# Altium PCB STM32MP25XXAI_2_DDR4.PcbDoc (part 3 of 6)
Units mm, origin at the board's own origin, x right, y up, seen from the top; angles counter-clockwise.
Board outline 172 x 137 mm, 4 copper layers (Top Layer, Signal Layer 1, Signal Layer 2, Bottom Layer), stack 1.614 mm thick; 241 components, 153 nets, 1312 pads, 924 vias.
Unrouted connection lines stored in the file: 13.
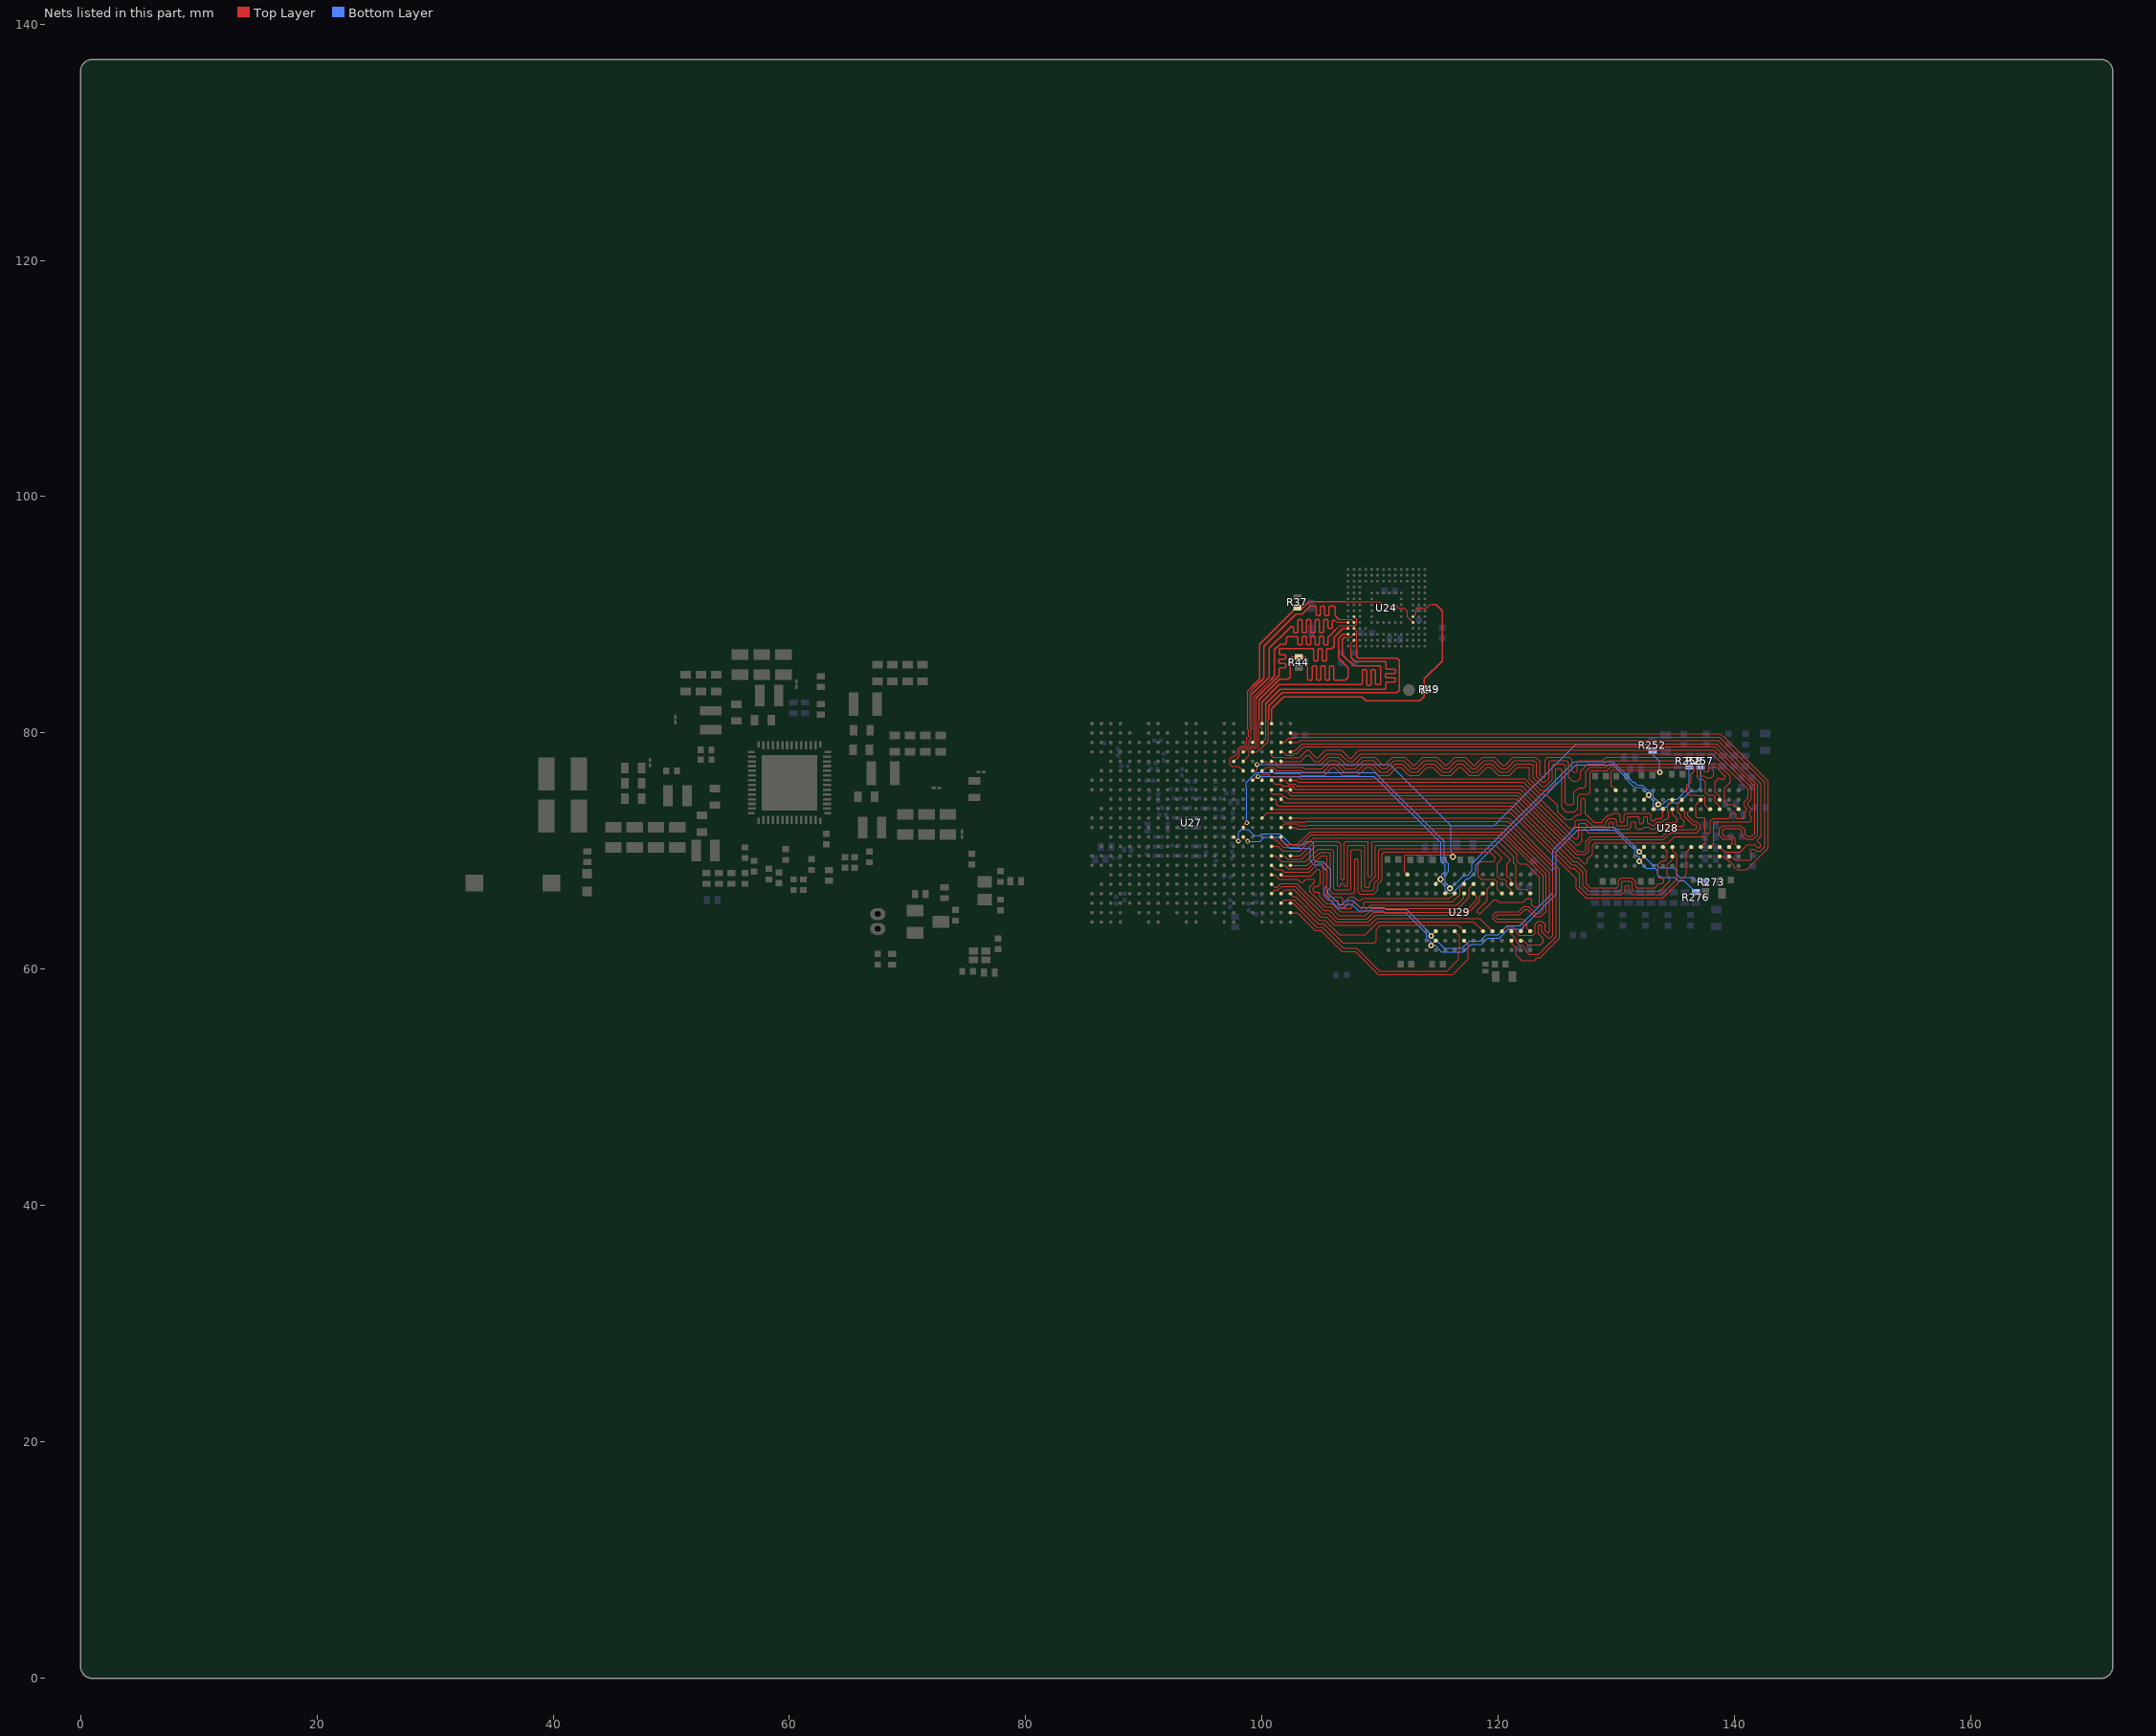
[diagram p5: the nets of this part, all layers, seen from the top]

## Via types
v1: diameter 0.55, hole 0.35, Top Layer to Bottom Layer, 432 vias
v2: diameter 0.4, hole 0.2, Top Layer to Bottom Layer, tented both sides, 202 vias
v3: diameter 0.5, hole 0.2, Top Layer to Bottom Layer, 146 vias
v4: diameter 0.5, hole 0.25, Top Layer to Bottom Layer, 144 vias

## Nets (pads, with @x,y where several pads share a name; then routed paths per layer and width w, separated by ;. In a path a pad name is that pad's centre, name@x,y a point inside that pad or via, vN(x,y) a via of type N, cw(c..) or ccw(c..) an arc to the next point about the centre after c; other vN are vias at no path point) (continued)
DDR_CSN: R273.1 U27.N16 U28.L7 U29.L7 | length 57.8
  Top Layer w0.09: U27.N16@97.6,71.2 97.625,71.2 97.975,70.85 v2(98,70.85) ; v4(114.3,62.825) 114.332,62.825 114.669,63.163 U29.L7@114.669,63.224 ; v4@131.963,69.928 132.301,70.266 U28.L7@132.301,70.327
  Bottom Layer w0.09: v2(98,70.85) 98,71.6 98.25,71.85 98.8,71.85 99.352,71.298 99.779,71.298 99.941,71.46 101.546,71.46 102.453,70.553 103.528,70.553 103.8,70.825 104.25,70.825 104.371,70.704 104.371,69.286 104.55,69.108 105.14,69.108 105.805,68.443 105.805,66.98 105.575,66.75 105.575,66.444 106.54,65.479 106.78,65.479 107.125,65.825 107.675,65.825 108.275,65.225 110.332,65.225 110.497,65.06 112.215,65.06 114.3,62.975 v4(114.3,62.825) 114.3,62.775 114.65,62.425 114.754,62.425 115.407,61.772 116.937,61.772 117.57,62.405 118.464,62.405 118.987,62.928 119.976,62.928 120.741,63.693 121.837,63.693 124.62,66.476 124.62,70.106 126.564,72.05 129.853,72.05 131.368,70.535 131.911,69.991 131.911,69.978 131.925,69.964 v4(131.925,69.95) 133.036,68.839 133.4,68.839 133.632,68.607 134.35,68.607 ; 134.35,68.606 134.853,68.606 135.095,68.364 135.095,68.046 135.337,67.805 136.42,67.805 136.85,67.375 R273.1@137.55,67.375
DDR_DQ0: U27.W22 U29.F7 | length 18.5
  Top Layer w0.09: U27.W22@102.4,66.4 102.615,66.185 102.82,66.185 104.862,64.144 105.339,64.144 106.556,62.927 108.753,62.927 109.836,64.01 117.908,64.01 U29.F7@118.682,63.237
DDR_DQ1: U27.Y21 U29.H7 | length 18.5
  Top Layer w0.09: U27.Y21@101.6,65.6 101.6,65.628 101.867,65.895 102.7,65.895 104.741,63.854 105.219,63.854 106.826,62.246 109.511,62.246 109.669,62.405 109.669,63.377 110.012,63.72 116.596,63.72 U29.H7@117.094,63.222
DDR_DQ2: U27.Y22 U29.J7 | length 19.6
  Top Layer w0.09: U27.Y22@102.4,65.6 102.419,65.581 102.604,65.581 104.621,63.564 105.098,63.564 106.884,61.778 108.022,61.778 109.953,59.847 115.648,59.847 116.651,60.851 116.651,61.417 116.695,61.461 116.695,62.82 U29.J7@116.294,63.222
DDR_DQ3: U27.AA22 U29.H8 | length 19.5
  Top Layer w0.09: U27.AA22@102.4,64.8 102.975,64.8 104.501,63.274 104.978,63.274 106.764,61.488 107.902,61.488 109.843,59.547 116.149,59.547 117.453,60.851 117.453,62.063 U29.H8@117.094,62.422
DDR_DQ4: U27.T21 U29.J3 | length 20
  Top Layer w0.09: U27.T21@101.6,68.8 101.942,68.8 102.237,68.505 103.899,68.505 104.992,69.599 105.381,69.599 105.501,69.478 105.501,66.319 105.686,66.134 106.676,66.134 106.835,65.974 106.835,65.53 106.934,65.432 107.071,65.432 107.232,65.593 107.232,65.957 107.413,66.137 107.785,66.137 108.072,65.85 108.382,65.85 108.536,66.003 115.875,66.003 U29.J3@116.294,66.422
DDR_DQ5: U27.T20 U29.H2 | length 22.2
  Top Layer w0.09: U27.T20@100.8,68.8 101.182,68.418 101.67,68.418 101.873,68.215 104.019,68.215 104.777,68.973 105.038,68.973 105.139,68.872 105.139,68.517 105.211,68.445 105.211,66.198 105.566,65.844 106.371,65.844 106.423,65.791 106.423,65.463 106.744,65.142 107.523,65.142 107.576,65.195 107.576,65.527 107.706,65.658 107.848,65.658 108.364,65.142 108.498,65.142 108.612,65.256 108.612,65.628 108.697,65.713 116.104,65.713 116.735,66.345 116.735,66.864 U29.H2@117.094,67.222
DDR_DQ6: U27.U21 U29.H3 | length 20.3
  Top Layer w0.09: U27.U21@101.604,68.004 101.682,67.925 104.139,67.925 104.682,68.468 104.778,68.468 104.921,68.325 104.921,67.221 104.7,67 104.463,67 104.315,66.852 104.315,66.684 104.462,66.537 104.773,66.537 104.888,66.422 104.888,66.111 105.446,65.554 105.923,65.554 106.624,64.852 108.618,64.852 109.189,65.423 116.482,65.423 117.094,66.035 U29.H3@117.094,66.422
DDR_DQ7: U27.U20 U29.G2 | length 21.4
  Top Layer w0.09: U27.U20@100.8,68 101.078,68 101.452,67.626 103.005,67.626 103.231,67.4 103.475,67.4 103.7,67.626 104.375,67.626 104.428,67.573 104.428,67.375 104.025,66.972 104.025,66.564 105.326,65.264 105.803,65.264 106.504,64.562 108.738,64.562 109.309,65.133 116.602,65.133 117.544,66.074 117.544,66.872 U29.G2@117.894,67.222
DDR_DQ8: U27.M21 U29.B8 | length 36
  Top Layer w0.09: U27.M21@101.6,72 101.903,72.303 102.947,72.303 103.083,72.168 103.776,72.168 103.826,72.217 120.651,72.217 124.615,68.253 124.615,62.892 124.4,62.676 124.174,62.676 123.679,63.171 123.679,63.692 123.59,63.78 123.468,63.78 123.384,63.696 123.384,62.988 123.795,62.577 123.795,62.32 123.55,62.075 122.461,62.075 122.151,62.386 121.93,62.386 U29.B8@121.894,62.422
DDR_DQ9: U27.M22 U29.D7 | length 34.8
  Top Layer w0.09: U27.M22@102.4,72 102.84,72 102.963,71.878 103.896,71.878 103.946,71.927 120.531,71.927 124.325,68.133 124.325,63.15 124.255,63.08 124.18,63.08 123.969,63.291 123.969,63.812 123.711,64.07 123.348,64.07 123.094,63.817 123.094,63.063 122.908,62.877 121.751,62.877 121.474,63.154 121.474,63.339 121.241,63.573 120.644,63.573 U29.D7@120.294,63.222
DDR_DQ10: U27.L21 U29.C7 | length 36.4
  Top Layer w0.09: U27.L21@101.6,72.8 101.9,72.5 103.16,72.5 103.203,72.458 103.656,72.458 103.706,72.507 120.771,72.507 124.905,68.373 124.905,62.771 123.411,61.277 122.596,61.277 122.321,61.552 122.321,61.708 122.007,62.022 121.806,62.022 121.521,62.307 121.521,62.523 121.094,62.951 U29.C7@121.094,63.222
DDR_DQ11: U27.L22 U29.C8 | length 36.5
  Top Layer w0.09: U27.L22@102.403,72.797 120.891,72.797 125.195,68.493 125.195,62.651 123.531,60.987 123.257,60.987 123.025,60.755 121.984,60.755 121.984,60.758 121.507,61.234 121.507,61.777 121.15,62.134 121.15,62.375 U29.C8@121.1,62.425
DDR_DQ12: U27.T22 U29.D3 | length 35.7
  Top Layer w0.09: U27.T22@102.4,68.8 103.783,68.8 104.872,69.889 105.737,69.889 105.791,69.835 105.791,66.585 105.949,66.427 107.716,66.427 107.827,66.538 107.827,69.263 107.91,69.347 108.01,69.347 108.123,69.233 108.123,66.54 108.296,66.367 109.46,66.367 109.78,66.687 109.78,67.164 110.164,67.547 110.164,69.788 110.313,69.937 119.279,69.937 119.719,69.497 119.719,69.239 119.587,69.108 118.533,69.108 118.305,68.88 118.305,67.858 118.541,67.622 119.665,67.622 119.924,67.363 119.924,66.792 U29.D3@120.294,66.422
DDR_DQ13: U27.R20 U29.C3 | length 37.4
  Top Layer w0.09: U27.R20@100.8,69.6 101.138,69.6 101.636,69.102 103.675,69.102 104.765,70.192 105.844,70.192 106.081,69.955 106.081,66.825 106.188,66.717 107.424,66.717 107.537,66.83 107.537,70.029 107.653,70.145 108.296,70.145 108.413,70.028 108.413,66.754 108.51,66.657 109.34,66.657 109.49,66.807 109.49,67.284 109.874,67.667 109.874,70.049 110.052,70.227 119.483,70.227 120.263,69.447 120.269,69.447 120.269,69.337 119.902,68.97 119.902,67.875 120.149,67.628 120.538,67.628 120.694,67.472 120.694,67.085 121.08,66.698 121.08,66.436 U29.C3@121.094,66.422
DDR_DQ14: U27.R21 U29.C2 | length 36.8
  Top Layer w0.09: U27.R21@101.6,69.6 101.893,69.6 102.189,69.304 103.346,69.304 104.56,70.517 106.284,70.517 106.371,70.431 106.371,67.089 106.453,67.007 106.566,67.007 106.661,67.102 106.661,67.233 106.737,67.309 106.852,67.309 106.957,67.204 106.957,67.082 107.031,67.007 107.158,67.007 107.247,67.096 107.247,70.431 107.333,70.517 108.633,70.517 108.703,70.447 108.703,67.035 108.791,66.947 109.031,66.947 109.121,67.037 109.121,67.358 109.584,67.821 109.584,70.439 109.662,70.517 119.769,70.517 120.994,69.292 120.994,69.186 120.704,68.897 120.704,67.924 121.094,67.534 U29.C2@121.094,67.222
DDR_DQ15: U27.R22 U29.A3 | length 35.9
  Top Layer w0.09: U27.R22@102.4,69.6 103.232,69.6 104.44,70.807 106.441,70.807 106.661,70.587 106.661,67.682 106.743,67.599 106.876,67.599 106.957,67.68 106.957,70.705 107.059,70.807 108.94,70.807 108.993,70.754 108.993,67.867 109.046,67.814 109.167,67.814 109.294,67.941 109.294,70.754 109.346,70.807 120.01,70.807 121.286,69.532 121.286,68.986 121.495,68.776 121.495,66.99 121.709,66.776 122.34,66.776 U29.A3@122.694,66.422
DDR_DQ16: U27.D20 U28.D7 | length 52.3
  Top Layer w0.09: U27.D20@100.8,78.4 100.8,78.074 100.912,77.962 ; 100.913,77.963 101.838,77.963 101.908,77.892 103.143,77.892 103.791,78.54 103.925,78.54 104.573,77.892 104.712,77.892 105.36,78.54 106.715,78.54 107.399,77.856 107.546,77.856 108.231,78.54 138.22,78.54 141.412,75.348 141.412,74.373 ; U28.D7@137.925,70.35 137.925,70.366 138.23,70.67 138.23,72.412 138.282,72.465 141.261,72.465 141.413,72.617 141.413,72.863 141.236,73.04 141.236,73.285 141.413,73.462 141.413,73.593 141.093,73.913 141.093,74.052 141.413,74.372
DDR_DQ17: U27.C22 U28.C7 | length 50.9
  Top Layer w0.09: U27.C22@102.4,79.2 103.106,79.2 103.277,79.37 138.564,79.37 142.243,75.691 142.243,71.27 141.949,70.976 141.949,70.826 142.191,70.585 142.191,70.427 142.067,70.304 141.924,70.304 141.703,70.525 141.072,70.525 140.468,69.921 139.13,69.921 U28.C7@138.725,70.325
DDR_DQ18: U27.C21 U28.B8 | length 52.6
  Top Layer w0.09: U27.C21@101.6,79.2 101.897,79.2 102.272,79.575 102.725,79.575 102.811,79.66 138.684,79.66 142.533,75.812 142.533,70.359 142.188,70.014 141.804,70.014 141.631,70.187 141.402,70.187 141.318,70.103 141.318,69.932 141.47,69.78 141.47,69.366 141.332,69.228 140.047,69.228 139.78,69.495 139.58,69.495 U28.B8@139.525,69.55
DDR_DQ19: U27.B22 U28.C8 | length 53.2
  Top Layer w0.09: U27.B22@102.4,80 102.45,79.95 138.804,79.95 139.04,79.715 142.823,75.932 142.823,70.239 141.014,68.43 140.193,68.43 139.93,68.693 139.93,68.798 139.568,69.16 139.463,69.16 139.073,69.55 U28.C8@138.725,69.55
DDR_DQ20: U27.F20 U28.D3 | length 54.2
  Top Layer w0.09: U27.F20@100.8,76.8 101.025,76.575 103.14,76.575 103.309,76.406 105.277,76.406 105.961,77.09 106.115,77.09 106.799,76.406 108.147,76.406 108.831,77.09 109.181,77.09 109.865,76.406 110.711,76.406 111.395,77.09 111.74,77.09 112.424,76.406 113.261,76.406 113.945,77.09 114.465,77.09 115.149,76.406 115.986,76.406 116.67,77.09 116.843,77.09 117.527,76.406 118.352,76.406 119.036,77.09 119.305,77.09 119.989,76.406 120.936,76.406 121.62,77.09 122.6,77.09 122.646,77.045 122.646,76.1 123.574,75.172 124.284,75.172 124.865,75.753 124.865,76.89 125,77.025 125.225,77.025 125.376,76.875 125.376,73.68 125.721,73.335 126.42,73.335 126.7,73.615 126.7,74.601 126.925,74.825 127.6,74.825 127.755,74.98 127.755,76.67 127.881,76.796 129.196,76.796 129.49,77.09 136.46,77.09 136.545,77.005 136.545,76.795 136.3,76.55 136.3,75.9 135.95,75.55 135.95,74.96 136.15,74.761 136.786,74.761 136.852,74.695 137.323,74.695 137.47,74.548 137.47,73.897 137.818,73.55 U28.D3@137.925,73.55
DDR_DQ21: U27.F19 U28.C3 | length 54.6
  Top Layer w0.09: U27.F19@100,76.8 100.039,76.8 100.339,77.1 100.924,77.1 101.199,76.825 103.3,76.825 103.429,76.696 105.157,76.696 105.841,77.38 106.235,77.38 106.919,76.696 108.027,76.696 108.711,77.38 109.301,77.38 109.985,76.696 110.591,76.696 111.275,77.38 111.86,77.38 112.544,76.696 113.141,76.696 113.825,77.38 114.585,77.38 115.269,76.696 115.866,76.696 116.55,77.38 116.963,77.38 117.647,76.696 118.232,76.696 118.916,77.38 119.425,77.38 120.109,76.696 120.816,76.696 121.5,77.38 122.821,77.38 122.936,77.265 122.936,76.22 123.694,75.462 123.962,75.462 124.575,76.075 124.575,77.25 124.706,77.38 125.52,77.38 125.666,77.235 125.666,74.1 125.816,73.95 126.285,73.95 126.41,74.075 126.41,74.993 126.793,75.375 127.25,75.375 127.4,75.525 127.4,76.75 127.736,77.086 129.076,77.086 129.37,77.38 136.745,77.38 136.835,77.29 136.835,76.785 ; 136.835,76.765 136.835,76.24 136.98,76.095 137.289,76.095 137.52,75.864 137.52,75.848 137.527,75.842 137.527,75.644 137.528,75.642 137.528,74.983 137.537,74.974 137.537,74.964 137.768,74.733 137.778,74.733 137.781,74.73 138.161,74.73 138.325,74.566 138.325,74.188 138.712,73.801 U28.C3@138.712,73.539
DDR_DQ22: U27.E19 U28.C2 | length 54
  Top Layer w0.09: U27.E19@100,77.6 100.376,77.6 100.676,77.3 101.117,77.3 101.317,77.1 103.435,77.1 103.549,76.986 105.036,76.986 105.721,77.67 106.355,77.67 107.039,76.986 107.907,76.986 108.591,77.67 109.421,77.67 110.105,76.986 110.47,76.986 111.155,77.67 111.98,77.67 112.665,76.986 113.02,76.986 113.705,77.67 114.705,77.67 115.39,76.986 115.745,76.986 116.43,77.67 117.083,77.67 117.767,76.986 118.111,76.986 118.796,77.67 119.545,77.67 120.229,76.986 120.695,76.986 121.38,77.67 123.009,77.67 123.226,77.454 123.226,76.34 123.741,75.825 123.915,75.825 124.275,76.185 124.275,77.55 124.396,77.67 125.75,77.67 125.957,77.464 125.957,76.268 126.289,75.937 126.673,75.937 126.962,76.226 126.962,76.77 127.568,77.376 128.956,77.376 129.25,77.67 136.955,77.67 137.125,77.5 137.125,76.462 137.2,76.387 137.417,76.387 137.608,76.196 138,76.196 138.225,76.421 138.225,76.75 138.09,76.885 138.09,77.065 138.155,77.13 138.4,77.13 139.204,76.326 139.204,76.204 139.095,76.095 138.925,76.095 138.845,76.175 138.642,76.175 138.323,75.856 138.323,74.978 138.568,74.733 138.63,74.733 138.725,74.637 U28.C2@138.725,74.35
DDR_DQ23: U27.E20 U28.A3 | length 53.5
  Top Layer w0.09: U27.E20@100.8,77.6 101.1,77.6 101.4,77.3 104.94,77.3 105.601,77.96 106.475,77.96 107.159,77.276 107.787,77.276 108.471,77.96 109.541,77.96 110.225,77.276 110.35,77.276 111.035,77.96 112.1,77.96 112.785,77.276 112.9,77.276 113.585,77.96 114.825,77.96 115.51,77.276 115.625,77.276 116.31,77.96 117.203,77.96 117.887,77.276 117.991,77.276 118.676,77.96 119.665,77.96 120.349,77.276 120.575,77.276 121.26,77.96 123.164,77.96 123.516,77.608 123.516,76.46 123.778,76.198 123.878,76.198 123.95,76.27 123.95,77.725 124.186,77.96 125.99,77.96 126.247,77.703 126.247,76.798 126.35,76.695 126.592,76.695 126.672,76.775 126.672,77.499 126.839,77.666 128.836,77.666 129.13,77.96 137.115,77.96 137.425,77.65 137.425,76.788 137.494,76.719 137.719,76.719 137.8,76.8 137.8,77.3 137.92,77.42 138.52,77.42 139.625,76.315 139.625,75.862 139.137,75.374 139.137,74.086 139.278,73.945 139.905,73.945 U28.A3@140.325,73.525
DDR_DQ24: U27.G19 U28.J3 | length 42.2
  Top Layer w0.09: U27.G19@100,76 100,76.4 100.1,76.5 100.505,76.5 100.71,76.295 103.009,76.295 103.188,76.116 122.219,76.116 123.543,74.793 124.058,74.793 125.002,73.848 125.002,73.333 125.661,72.675 126.209,72.675 126.644,73.11 126.925,73.11 127,73.185 127,74.388 127.086,74.474 127.259,74.474 127.362,74.37 127.362,73.165 128.092,72.435 128.763,72.435 128.816,72.488 128.816,72.622 129.249,73.055 129.559,73.055 129.704,73.2 130.125,73.2 130.306,73.02 130.306,72.475 130.346,72.435 130.525,72.435 130.625,72.535 130.625,73.046 130.779,73.2 132.748,73.2 132.9,73.048 132.9,72.67 133.01,72.56 ; 133.011,72.56 133.14,72.56 133.358,72.778 133.77,72.778 133.925,72.933 U28.J3@133.925,73.55
DDR_DQ25: U27.G22 U28.H2 | length 39.5
  Top Layer w0.09: U27.G22@102.4,76 102.41,75.99 102.904,75.99 103.068,75.826 122.099,75.826 126.009,71.916 126.264,71.916 126.52,72.173 126.52,72.54 126.628,72.648 127.458,72.648 127.961,72.145 128.996,72.145 129.106,72.255 129.106,72.502 129.369,72.765 129.846,72.765 130.016,72.595 130.016,72.21 130.08,72.145 130.88,72.145 130.935,72.2 130.935,72.824 131.021,72.91 131.816,72.91 131.925,72.8 131.925,72.398 131.998,72.325 132.131,72.325 132.3,72.495 132.3,72.85 132.36,72.91 132.554,72.91 132.61,72.853 132.61,72.415 132.7,72.325 132.835,72.325 133.015,72.145 133.135,72.145 133.478,72.488 133.89,72.488 134.093,72.69 134.267,72.69 134.425,72.849 134.425,73.275 134.329,73.371 134.329,73.929 U28.H2@134.725,74.325
DDR_DQ26: U27.G21 U28.H3 | length 40.5
  Top Layer w0.09: U27.G21@101.6,76 101.9,76 102.2,75.7 102.784,75.7 102.948,75.536 121.969,75.536 126.424,71.08 126.678,71.08 126.81,71.213 126.81,72.251 126.918,72.358 127.338,72.358 127.841,71.855 129.287,71.855 129.396,71.964 129.396,72.382 129.489,72.475 129.601,72.475 129.726,72.35 129.726,71.951 129.822,71.855 131.03,71.855 131.225,72.05 131.225,72.39 131.319,72.483 131.55,72.483 131.627,72.407 131.627,72.008 131.78,71.855 132.165,71.855 132.345,72.035 132.715,72.035 132.895,71.855 133.255,71.855 133.598,72.198 134.011,72.198 134.213,72.4 135.008,72.4 135.135,72.526 135.135,72.715 134.725,73.124 U28.H3@134.725,73.55
DDR_DQ27: U27.G20 U28.G2 | length 41.2
  Top Layer w0.09: U27.G20@100.8,76 101.1,75.7 101.527,75.7 101.727,75.5 102.574,75.5 102.828,75.246 121.848,75.246 126.543,70.552 126.809,70.552 127.1,70.843 127.1,71.777 127.208,71.885 127.366,71.885 127.45,71.8 127.45,71.715 127.6,71.565 133.375,71.565 133.718,71.908 134.131,71.908 134.328,72.105 135.59,72.105 135.7,72.216 135.7,72.515 135.425,72.791 135.425,73.051 135.18,73.295 135.18,73.98 U28.G2@135.525,74.325
DDR_DQ28: U27.J21 U28.J7 | length 41.5
  Top Layer w0.09: U27.J21@101.6,74.4 101.614,74.4 101.892,74.122 121.368,74.122 126.35,69.14 126.635,69.14 127.45,68.325 127.45,67.229 127.779,66.9 129.995,66.9 130.152,67.057 130.152,67.502 130.4,67.75 131.301,67.75 131.63,67.421 131.63,66.997 131.728,66.9 133.223,66.9 133.566,67.243 133.858,67.243 134,67.385 134,67.525 133.8,67.725 133.6,67.725 133.505,67.82 133.505,68.86 133.768,69.123 133.898,69.123 133.98,69.205 134.068,69.205 134.303,69.439 134.303,69.973 U28.J7@133.925,70.35
DDR_DQ29: U27.J20 U28.H8 | length 41.8
  Top Layer w0.09: U27.J20@100.8,74.4 101.125,74.4 101.2,74.325 101.2,74 101.368,73.832 121.248,73.832 126.23,68.85 126.515,68.85 127.16,68.205 127.16,67.109 127.659,66.61 130.312,66.61 130.442,66.74 130.442,67.382 130.52,67.46 131.181,67.46 131.34,67.301 131.34,66.765 131.496,66.61 133.64,66.61 134.5,67.47 134.5,67.775 134.3,67.975 134.3,68.869 134.725,69.294 U28.H8@134.725,69.55
DDR_DQ30: U27.K20 U28.H7 | length 42.5
  Top Layer w0.09: U27.K20@100.8,73.6 100.858,73.542 121.128,73.542 126.11,68.56 126.395,68.56 126.87,68.085 126.87,66.988 127.539,66.32 130.432,66.32 130.732,66.62 130.732,67.028 130.8,67.096 130.998,67.096 131.05,67.043 131.05,66.584 131.314,66.32 133.795,66.32 135.1,67.625 135.1,69.692 134.725,70.067 U28.H7@134.725,70.35
DDR_DQ31: U27.L19 U28.F7 | length 42.9
  Top Layer w0.09: U27.L19@100,72.8 100.442,73.242 121.018,73.242 126.58,67.68 126.58,66.868 127.419,66.03 133.93,66.03 135.926,68.026 135.926,69.951 U28.F7@136.325,70.35
DDR_DQM0: U27.W21 U29.E7 | length 19.9
  Top Layer w0.09: U27.W21@101.6,66.4 101.921,66.721 102.694,66.721 104.982,64.434 105.459,64.434 106.16,63.732 109.138,63.732 109.706,64.3 118.416,64.3 U29.E7@119.494,63.222
DDR_DQM1: U27.P20 U29.E2 | length 36.9
  Top Layer w0.09: U27.P20@100.8,70.4 101.34,70.4 101.713,70.028 103.22,70.028 103.225,70.033 103.24,70.033 104.304,71.097 120.187,71.097 121.575,69.709 121.575,69.135 121.807,68.904 122.381,68.904 123.495,67.789 123.495,65.445 123.34,65.29 123.015,65.29 122.842,65.462 122.842,65.833 122.681,65.994 122.434,65.994 122.107,65.667 120.037,65.667 119.827,65.877 119.627,65.877 118.45,64.7 118.346,64.7 118.2,64.847 118.2,64.991 119.069,65.86 119.069,66.797 U29.E2@119.494,67.222
DDR_DQM2: U27.E21 U28.E2 | length 53.4
  Top Layer w0.09: U27.E21@101.6,77.6 103.26,77.6 103.76,78.1 103.956,78.1 104.456,77.6 104.83,77.6 105.48,78.25 106.595,78.25 107.279,77.566 107.666,77.566 108.351,78.25 138.1,78.25 141.122,75.228 141.122,74.492 140.803,74.173 140.803,73.793 141.002,73.595 141.002,73.461 140.803,73.263 140.803,72.875 140.683,72.755 140.2,72.755 140.11,72.845 140.11,73.115 139.975,73.25 139.784,73.25 139.625,73.091 139.625,72.9 139.48,72.755 138.162,72.755 137.94,72.532 137.94,71.606 137.844,71.511 137.594,71.511 137.507,71.597 137.507,72.722 137.4,72.829 136.816,72.829 136.703,72.942 136.703,73.923 137.128,74.348 U28.E2@137.125,74.35
DDR_DQM3: U27.H20 U28.E7 | length 42.1
  Top Layer w0.09: U27.H20@100.8,75.2 100.8,74.898 100.876,74.822 101.616,74.822 101.79,74.648 101.947,74.648 102.183,74.412 121.488,74.412 126.47,69.43 126.755,69.43 127.285,68.9 127.421,68.9 127.53,69.01 127.53,69.335 127.965,69.769 127.965,70.475 127.965,70.491 128.169,70.695 134.353,70.695 134.88,71.222 137.429,71.222 137.525,71.125 137.525,70.725 U28.E7@137.125,70.325
DDR_DQS0_N: U27.W20 U29.F3 | length 20.6
  Top Layer w0.09: U27.W20@100.8,66.4 101.082,66.682 101.343,66.682 101.682,67.022 102.804,67.022 105.102,64.724 105.579,64.724 106.28,64.022 109.018,64.022 109.589,64.593 117.252,64.593 118.418,65.758 118.418,66.146 U29.F3@118.694,66.422
DDR_DQS0_P: U27.V20 U29.G3 | length 20.2
  Top Layer w0.09: U27.V20@100.8,67.2 101.068,66.932 101.239,66.932 101.579,67.272 102.907,67.272 105.205,64.974 105.682,64.974 106.384,64.272 108.914,64.272 109.486,64.843 117.149,64.843 118.168,65.862 118.168,66.141 117.894,66.415 U29.G3@117.894,66.422
DDR_DQS1_N: U27.N21 U29.A7 | length 36.6
  Top Layer w0.09: U27.N21@101.6,71.2 101.6,70.904 101.936,70.568 102.996,70.568 104.066,71.637 120.411,71.637 124.035,68.013 124.035,64.911 123.586,64.462 123.069,64.462 122.455,65.076 122.244,65.076 121.783,64.614 119.904,64.614 119.8,64.511 119.8,64.352 119.896,64.257 122.056,64.257 122.41,63.903 122.41,63.506 U29.A7@122.694,63.222
DDR_DQS1_P: U27.N20 U29.B7 | length 36.9
  Top Layer w0.09: U27.N20@100.8,71.2 101.07,70.93 101.22,70.93 101.833,70.318 103.1,70.318 104.169,71.387 120.307,71.387 123.785,67.909 123.785,65.015 123.482,64.712 123.173,64.712 122.558,65.326 122.141,65.326 121.679,64.864 119.8,64.864 119.55,64.615 119.55,64.249 119.792,64.007 121.952,64.007 122.16,63.799 122.16,63.502 U29.B7@121.882,63.224
DDR_DQS2_N: U27.D22 U28.A7 | length 51.7
  Top Layer w0.09: U27.D22@102.4,78.4 102.461,78.4 102.581,78.52 102.836,78.52 103.397,79.08 138.444,79.08 141.953,75.571 141.953,71.39 141.57,71.008 140.936,71.008 140.625,71.318 140.625,71.675 140.377,71.923 139.096,71.923 138.972,71.8 138.972,71.398 139.09,71.28 139.849,71.28 140.058,71.071 140.058,70.592 U28.A7@140.325,70.325
DDR_DQS2_P: U27.D21 U28.B7 | length 52.2
  Top Layer w0.09: U27.D21@101.6,78.4 101.605,78.395 101.816,78.395 102.111,78.1 102.575,78.1 102.745,78.27 102.94,78.27 103.5,78.83 138.34,78.83 141.703,75.468 141.703,71.494 141.467,71.258 141.04,71.258 140.875,71.422 140.875,71.778 140.481,72.173 138.992,72.173 138.722,71.903 138.722,71.295 138.987,71.03 139.746,71.03 139.808,70.968 139.808,70.658 U28.B7@139.513,70.363
DDR_DQS3_N: U27.H21 U28.F3 | length 41.5
  Top Layer w0.09: U27.H21@101.533,75.175 102.001,75.175 102.47,74.706 121.62,74.706 126.604,69.721 127.379,69.721 127.658,70 127.658,70.723 127.92,70.985 133.983,70.985 134.563,71.565 136.748,71.565 137.064,71.88 137.064,72.236 136.8,72.499 136.552,72.499 136.05,73.001 136.05,73.275 U28.F3@136.325,73.55
DDR_DQS3_P: U27.H22 U28.G3 | length 40.1
  Top Layer w0.09: U27.H22@102.4,75.2 102.4,75.136 102.581,74.956 121.723,74.956 126.708,69.971 127.276,69.971 127.408,70.104 127.408,70.827 127.817,71.235 133.88,71.235 134.46,71.815 136.645,71.815 136.814,71.984 136.814,72.132 136.697,72.249 136.449,72.249 135.8,72.898 135.8,73.275 U28.G3@135.525,73.55
DDR_ODT: R258.1 U27.M17 U28.K3 U29.K3 | length 58.3
  Top Layer w0.09: U27.M17@98.4,72 98.437,72.037 98.437,72.211 98.625,72.4 v2(98.7,72.4) ; U29.K3@115.494,66.422 115.508,66.422 115.9,66.814 v4(115.9,66.848) ; U28.K3@133.125,73.525 133.14,73.525 133.525,73.911 v4(133.525,73.95)
  Bottom Layer w0.09: v2(98.7,72.4) 98.7,75.362 98.635,75.427 98.635,75.798 99.508,76.671 109.549,76.671 115.413,70.807 115.413,69.329 115.804,68.938 115.804,68.33 115.5,68.026 115.5,67.324 115.745,67.078 115.745,67.042 115.9,66.887 v4(115.9,66.848) 115.9,66.825 115.925,66.825 117.065,67.965 117.384,67.965 117.782,68.363 117.782,68.953 126.102,77.273 126.424,77.595 129.687,77.595 131.125,76.157 131.125,76.089 131.356,75.857 131.485,75.857 131.748,75.595 132.176,75.595 132.626,75.145 132.895,75.145 133.12,74.919 133.12,74.596 133.464,74.253 133.464,74.012 v4(133.525,73.95) ; v4@133.728,74.005 133.954,74.005 134.354,74.405 135.124,74.405 136.15,75.431 R258.1@136.15,77.175
DDR_RASN: R276.1 U27.N17 U28.L8 U29.L8 | length 55.7
  Top Layer w0.09: U27.N17@98.4,71.2 v2(98.775,70.825) ; v4(114.3,62.025) 114.3,62.055 U29.L8@114.669,62.424 ; v4@131.932,69.158 U28.L8@132.301,69.527
  Bottom Layer w0.09: v2(98.775,70.825) 99.833,70.825 100.178,71.17 101.426,71.17 102.333,70.263 104.029,70.263 104.081,70.21 104.081,69.166 104.43,68.818 105.02,68.818 105.515,68.322 105.515,67.1 105.285,66.87 105.285,66.324 106.42,65.189 106.9,65.189 107.245,65.535 107.555,65.535 108.155,64.935 110.212,64.935 110.357,64.79 112.132,64.79 113.905,63.017 113.905,62.589 114.064,62.43 114.195,62.43 114.275,62.35 114.275,62.05 v4(114.3,62.025) 114.636,62.025 115.191,61.47 117.045,61.47 117.69,62.115 118.584,62.115 119.107,62.638 120.096,62.638 120.861,63.403 121.957,63.403 124.91,66.356 124.91,69.986 126.724,71.8 129.821,71.8 131.276,70.345 131.289,70.345 131.52,70.114 131.52,70.101 131.53,70.091 131.53,69.786 131.762,69.555 131.87,69.555 131.925,69.5 v4(131.925,69.15) 132.526,68.549 133.26,68.549 133.495,68.314 133.495,68.046 133.737,67.805 133.75,67.805 133.75,67.804 134.928,67.804 135.217,67.515 135.702,67.515 136.692,66.525 R276.1@136.725,66.525
DDR_RESETN: R252.2 U27.F18 U28.P1 U29.P1 | length 56.2
  Top Layer w0.09: U27.F18@99.2,76.8 99.22,76.82 99.495,76.82 99.575,76.9 99.575,77 ; 99.575,77 v2(99.575,77.325) ; U29.P1@112.294,68.022 112.05,68.265 112.05,69.6 112.15,69.7 115.9,69.7 v4@116.075,69.525 ; U28.P1@129.925,75.15 129.532,75.543 129.532,76.749 129.633,76.85 133.392,76.85 133.567,76.675 v4(133.65,76.675)
  Bottom Layer w0.09: v2(99.575,77.325) 110.793,77.325 115.974,72.143 115.974,70.031 116.075,69.93 116.075,69.6 v4(116.15,69.525) ; 115.976,72.141 119.639,72.141 126.538,79.04 132.535,79.04 132.745,78.83 132.745,78.735 132.955,78.525 R252.2@133.05,78.525 133.104,78.471 133.104,78.124 133.65,77.578 v4(133.65,76.675)
DDR_WEN: R257.1 U27.G18 U28.L2 U29.L2 | length 54.8
  Top Layer w0.09: U27.G18@99.2,76 99.257,76 99.582,76.325 v2(99.65,76.325) ; U29.L2@114.694,67.222 114.694,67.27 v4@115.049,67.625 ; U28.L2@132.325,74.325 132.325,74.373 v4@132.68,74.728
  Bottom Layer w0.09: v2(99.65,76.325) 99.666,76.341 109.469,76.341 115.123,70.687 115.123,69.161 115.495,68.789 115.495,68.29 115.34,68.135 115.33,68.135 115.21,68.015 v4@115.21,67.845 ; v4@115.102,67.625 115.162,67.566 115.162,67.322 115.505,66.979 115.505,66.684 115.737,66.453 116.098,66.453 117.32,67.675 117.504,67.675 118.072,68.243 118.072,68.484 118.072,68.833 118.457,69.218 126.544,77.305 129.708,77.305 130.93,76.083 130.93,75.957 131.482,75.405 132.098,75.405 132.725,74.777 132.725,74.649 133.124,74.251 133.124,73.793 133.362,73.555 133.689,73.555 133.885,73.751 134.227,73.751 134.585,74.11 135.319,74.11 136.274,75.065 136.799,75.065 137.135,75.401 137.135,77.141 R257.1@137.1,77.175
  other v4: 115.1,67.625 132.725,74.75
eMMC.SDMMC2_CK: R49.1 U24.M6 U27.A20 | length 26.1
  Top Layer w0.09: U24.M6@112.775,89.85 113.025,90.1 113.025,90.454 113.171,90.6 113.925,90.6 114.175,90.85 114.375,90.85
  Top Layer w0.11: U27.A20@100.8,80.8 100.8,82.03 101.807,83.037 106.072,83.037 108.445,83.037 108.767,82.715 113.348,82.715 113.725,83.093 R49.1@113.725,83.685 113.725,84.582 115.25,86.107 115.25,90.35 114.75,90.85 114.375,90.85
eMMC.SDMMC2_CMD: R37.1 U24.M5 U27.F17 | length 28.4
  Top Layer w0.09: U27.F17@98.4,76.8 98.002,77.198 97.453,77.198 97.29,77.36 97.29,77.84 97.432,77.982 97.62,77.982 97.91,78.272 97.91,78.596 98.199,78.885 98.488,78.885 98.715,79.112 98.715,79.56 98.865,79.71 98.865,80.231 98.785,80.311 98.785,83.537 99.131,83.883 99.131,83.898 ; 107.071,91.1 109.975,91.1 110.3,90.775 111.35,90.775 111.525,90.6 112,90.6 112.3,90.3 112.3,89.825 U24.M5@112.775,89.35
  Top Layer w0.11: 99.124,83.891 99.131,83.898 99.185,83.952 99.185,83.966 99.694,84.475 99.787,84.568 99.787,87.507 102.287,90.007 102.88,90.6 R37.1@102.975,90.6 103.449,90.6 103.943,91.093 107.071,91.093
eMMC.SDMMC2_D0: R44.1 U24.A3 U27.B19 | length 25.9
  Top Layer w0.09: 99.75,81.05 99.695,80.995 99.695,80.674 100,80.369 U27.B19@100,80
  Top Layer w0.11: 99.75,81.05 99.75,82.8 101.491,84.541 102.178,84.541 102.363,84.725 102.363,86.308 102.482,86.428 R44.1@103.1,86.428 103.633,86.428 103.836,86.225 103.836,84.57 103.929,84.477 ; 103.932,84.474 103.929,84.477 ; U24.A3@107.275,88.35 106.824,88.35 106.475,88.001 106.475,86.332 107.27,85.537 107.27,84.724 107.023,84.477 106.406,84.477 106.162,84.477 106.071,84.568 106.071,85.579 105.98,85.67 105.798,85.67 105.707,85.579 105.707,84.566 105.616,84.475 105.434,84.475 105.343,84.566 105.343,85.593 105.252,85.684 105.07,85.684 104.979,85.593 104.979,84.566 104.888,84.475 104.706,84.475 104.615,84.566 104.615,85.593 104.524,85.684 104.342,85.684 104.251,85.593 104.251,84.568 104.16,84.477 104.105,84.477 103.929,84.477
eMMC.SDMMC2_D1: U24.A4 U27.E17 | length 24
  Top Layer w0.09: U27.E17@98.4,77.6 98.895,78.095 98.895,78.526 99.074,78.705 99.505,78.705 99.695,78.895 99.695,80.419 99.515,80.599 99.515,82.965 99.525,82.975
  Top Layer w0.11: 99.525,82.965 99.525,82.975 101.442,84.892 101.442,85.031 101.442,85.45 101.533,85.541 101.944,85.541 102.035,85.632 102.035,85.814 101.944,85.905 101.493,85.905 101.402,85.996 101.402,86.178 101.493,86.269 101.944,86.269 102.035,86.36 102.035,86.542 101.944,86.633 101.533,86.633 101.442,86.724 101.442,86.911 101.442,87.057 101.525,87.14 103.849,87.14 104.268,87.14 104.359,87.049 104.359,86.182 104.45,86.091 104.632,86.091 104.723,86.182 104.723,87.061 104.814,87.152 104.996,87.152 105.087,87.061 105.087,86.182 105.178,86.091 105.36,86.091 105.451,86.182 105.451,87.049 105.542,87.14 105.917,87.14 105.923,87.146 106.102,87.325 106.102,88.132 106.82,88.85 U24.A4@107.275,88.85
eMMC.SDMMC2_D2: U24.A5 U27.C18 | length 25.1
  Top Layer w0.09: 99.155,83.28 99.155,80.45 99.335,80.27 99.335,79.361 99.2,79.226 U27.C18@99.2,79.2 ; 106.195,89.516 106.353,89.358 107.267,89.358 U24.A5@107.275,89.35
  Top Layer w0.11: 99.155,83.28 100.606,84.731 100.606,87.166 102.247,88.807 102.446,89.006 102.575,89.006 102.666,88.915 102.666,88.55 102.757,88.459 102.939,88.459 103.03,88.55 103.03,89.502 103.121,89.593 103.303,89.593 103.394,89.502 103.394,88.55 103.485,88.459 103.667,88.459 103.758,88.55 103.758,89.502 103.849,89.593 104.031,89.593 104.122,89.502 104.122,88.55 104.213,88.459 104.395,88.459 104.486,88.55 104.486,89.502 104.577,89.593 104.759,89.593 104.85,89.502 104.85,88.55 104.941,88.459 105.123,88.459 105.214,88.55 105.214,89.502 105.305,89.593 105.487,89.593 105.578,89.502 105.578,88.917 105.669,88.826 105.851,88.826 105.942,88.917 105.942,89.425 106.033,89.516 106.103,89.516 106.195,89.516
eMMC.SDMMC2_D3: U24.B2 U27.C19 | length 23.9
  Top Layer w0.09: U27.C19@100,79.2 100.31,79.51 100.31,81.055 ; 107.525,86.9 107.525,87.6 U24.B2@107.775,87.85
  Top Layer w0.11: 100.31,81.055 100.299,81.065 100.299,82.474 101.545,83.72 110.396,83.72 110.461,83.784 110.461,83.796 110.461,84.215 110.552,84.306 111.194,84.306 111.285,84.397 111.285,84.579 111.194,84.67 110.539,84.67 110.448,84.761 110.448,84.943 110.539,85.034 111.194,85.034 111.285,85.125 111.285,85.307 111.194,85.398 110.552,85.398 110.461,85.489 110.461,85.916 110.461,85.974 110.396,86.038 107.887,86.038 107.525,86.4 107.525,86.9
eMMC.SDMMC2_D4: U24.B3 U27.A19 | length 24.8
  Top Layer w0.09: 107,88.1 107.525,88.1 U24.B3@107.775,88.35
  Top Layer w0.11: U27.A19@100,80.8 100,82.625 101.459,84.084 108.332,84.084 108.387,84.084 108.478,84.175 108.478,85.263 108.569,85.354 108.751,85.354 108.842,85.263 108.842,84.122 108.933,84.031 109.115,84.031 109.206,84.122 109.206,85.263 109.297,85.354 109.479,85.354 109.57,85.263 109.57,84.175 109.661,84.084 109.866,84.084 109.947,84.084 110.053,84.19 110.053,85.549 109.938,85.664 107.753,85.664 106.814,86.603 106.814,87.914 107,88.1
eMMC.SDMMC2_D5: U24.B4 U27.D18 | length 25.1
  Top Layer w0.09: U27.D18@99.2,78.4 99.562,78.4 99.872,78.71 99.948,78.71 100.49,79.252 100.51,79.272 100.51,81.16 100.55,81.2 ; U24.B4@107.775,88.85 108.025,88.6 108.025,87.75 108.025,87.15
  Top Layer w0.11: 100.55,81.2 100.55,82.275 101.684,83.409 106.072,83.409 111.428,83.409 111.596,83.577 111.596,86.171 111.422,86.345 108.142,86.345 108.025,86.462 108.025,87.15
eMMC.SDMMC2_D6: U24.B5 U27.E16 | length 23.9
  Top Layer w0.09: U27.E16@97.6,77.6 98.09,78.09 98.09,78.375 98.095,78.38 98.095,78.526 98.274,78.705 98.563,78.705 98.895,79.037 98.895,79.345 99.045,79.495 99.045,80.305 98.965,80.385 98.965,83.463 99.385,83.883 ; 106.499,89.612 106.803,89.612 106.815,89.6 107.525,89.6 U24.B5@107.775,89.35
  Top Layer w0.11: 99.385,83.883 99.977,84.475 100.173,84.671 100.173,87.357 102.876,90.06 103.393,90.06 104.072,90.739 104.491,90.739 104.582,90.648 104.582,90.022 104.673,89.931 104.855,89.931 104.946,90.022 104.946,90.659 105.037,90.75 105.219,90.75 105.31,90.659 105.31,90.022 105.401,89.931 105.583,89.931 105.674,90.022 105.674,90.648 105.765,90.739 106.071,90.739 106.179,90.63 106.195,90.615 106.195,89.916 106.499,89.612
eMMC.SDMMC2_D7: U24.B6 U27.D17 | length 24
  Top Layer w0.09: U27.D17@98.4,78.4 98.44,78.44 98.552,78.44 98.997,78.885 99.431,78.885 99.515,78.969 99.515,80.345 99.335,80.525 99.335,83.11 100.7,84.475 ; 106.195,88.716 106.579,89.1 107.879,89.1 108.025,89.246 108.025,89.6 U24.B6@107.775,89.85
  Top Layer w0.11: 100.7,84.475 101.049,84.824 101.049,87.051 101.524,87.526 101.95,87.525 102.049,87.624 102.049,88.051 102.171,88.172 102.52,88.172 102.939,88.172 103.03,88.081 103.03,87.56 103.121,87.469 103.303,87.469 103.394,87.56 103.394,88.107 103.485,88.198 103.667,88.198 103.758,88.107 103.758,87.56 103.849,87.469 104.031,87.469 104.122,87.56 104.122,88.107 104.213,88.198 104.395,88.198 104.486,88.107 104.486,87.56 104.577,87.469 104.759,87.469 104.85,87.56 104.85,88.107 104.941,88.198 105.123,88.198 105.214,88.107 105.214,87.56 105.305,87.469 105.487,87.469 105.578,87.56 105.578,88.099 105.726,88.247 106.195,88.716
